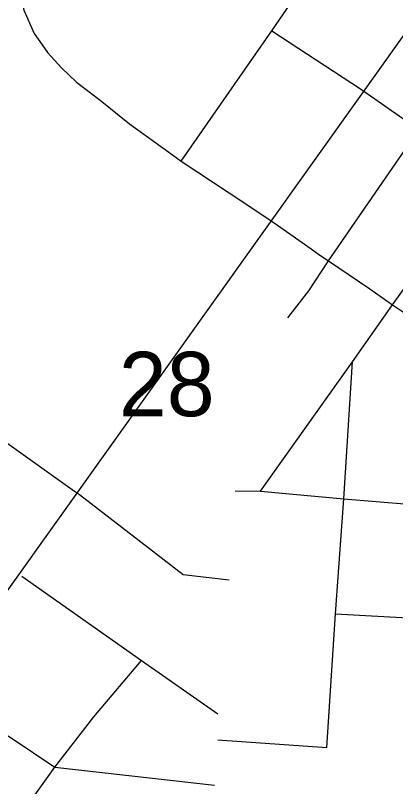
# Model space of a CAD drawing. Extents: x 0 to 34, y 0 to 22.
# Drawn here: x 5.747 to 5.994, y 17.023 to 17.525 of the extents above; entities that cross this region are included whole.
import ezdxf

# ---------------------------------------------------------------- set-up
doc = ezdxf.new("R2010")
doc.units = 0
for name, color, linetype in [('GM_X_City_Street', 7, 'Continuous'), ('GM_X_County_Road', 7, 'Continuous'), ('GM_X_Rail_Line', 7, 'Continuous'), ('GM_X_Section_Text', 7, 'Continuous'), ('GM_X_State_Route', 7, 'Continuous')]:
    doc.layers.add(name, color=color, linetype=linetype)

msp = doc.modelspace()

# ---------------------------------------------------------------- linework, layer by layer
at = {"layer": 'GM_X_City_Street'}
for p, q in [((5.6959, 17.27911), (5.78515, 17.21539)), ((5.95465, 17.13556), (6.03704, 17.13083)), ((5.87827, 17.05346), (5.94907, 17.04845))]:
    msp.add_line(p, q, dxfattribs=at)
for points in [[(5.92378, 17.32805), (5.93734, 17.34568), (5.95012, 17.36525), (6.00892, 17.45049), (6.01104, 17.45336), (6.05756, 17.51641)], [(5.78515, 17.21539), (5.78839, 17.21307), (5.85571, 17.16104), (5.88559, 17.15756)], [(5.94907, 17.04845), (5.95465, 17.13556), (5.96019, 17.21042)], [(5.75089, 17.15994), (5.82874, 17.10519), (5.87829, 17.07034)], [(5.75136, 16.99917), (5.75145, 17.0002), (5.75493, 17.01134), (5.7724, 17.03582), (5.79773, 17.06841), (5.82874, 17.10519)], [(5.69704, 17.0836), (5.74393, 17.0549), (5.7724, 17.03582), (5.87611, 17.02395)]]:
    msp.add_lwpolyline(points, dxfattribs=at)
at = {"layer": 'GM_X_County_Road'}
for p, q in [((5.91337, 17.5149), (5.97186, 17.60099)), ((5.85444, 17.43012), (5.91337, 17.5149)), ((5.91337, 17.5149), (5.97105, 17.47721)), ((5.99188, 17.3366), (6.05142, 17.42019)), ((5.96571, 17.29943), (5.99188, 17.3366)), ((5.90604, 17.21537), (5.96571, 17.29943)), ((5.96019, 17.21042), (5.96571, 17.29943))]:
    msp.add_line(p, q, dxfattribs=at)
for points in [[(5.97105, 17.47721), (6.00049, 17.4565), (6.00892, 17.45049), (6.01133, 17.44878)], [(5.88961, 17.21555), (5.90604, 17.21537), (5.96019, 17.21042), (6.04418, 17.20329), (6.1343, 17.19485), (6.13694, 17.1946), (6.20864, 17.19023)]]:
    msp.add_lwpolyline(points, dxfattribs=at)
at = {"layer": 'GM_X_Rail_Line'}
msp.add_lwpolyline([(5.19785, 15.33512), (5.23856, 15.69988), (5.25306, 15.832), (5.26931, 16.00821), (5.28851, 16.17841), (5.3068, 16.25578), (5.3233, 16.355), (5.32062, 16.40147), (5.32471, 16.46786), (5.38344, 16.63306), (5.40116, 16.66967), (5.70831, 17.10401), (6.13763, 17.70647), (6.20126, 17.80077), (6.22365, 17.82316), (6.26385, 17.83966), (6.33705, 17.85882)], dxfattribs=at)
at = {"layer": 'GM_X_State_Route'}
for points in [[(5.749, 17.55145), (5.74971, 17.5439), (5.75227, 17.52831), (5.75903, 17.51314), (5.76414, 17.50568)], [(5.76414, 17.50568), (5.76754, 17.50071), (5.7767, 17.49072), (5.78652, 17.48139), (5.80173, 17.46978), (5.82088, 17.4544), (5.84645, 17.4359)], [(5.84645, 17.4359), (5.85444, 17.43012), (5.88564, 17.40944), (5.91006, 17.39313)], [(5.91006, 17.39313), (5.91707, 17.38842), (5.93889, 17.37302), (5.94461, 17.36898), (5.95012, 17.36525), (5.97709, 17.34697), (5.99188, 17.3366), (5.99948, 17.33127), (6.01498, 17.3204)]]:
    msp.add_lwpolyline(points, dxfattribs=at)

# ---------------------------------------------------------------- texts
at = {"layer": 'GM_X_Section_Text'}
msp.add_text('28', height=0.041856, rotation=0, dxfattribs=at).set_placement((5.81396, 17.26411))

doc.saveas('drawing.dxf')
